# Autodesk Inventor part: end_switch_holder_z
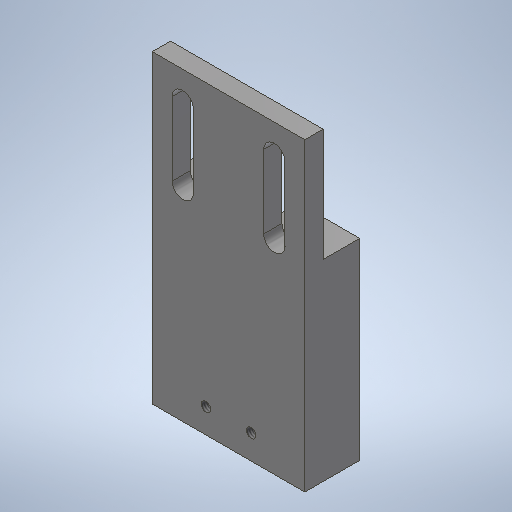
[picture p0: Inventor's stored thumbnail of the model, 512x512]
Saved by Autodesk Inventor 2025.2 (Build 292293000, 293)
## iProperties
Created: 2025-04
Part Number: end_switch_holder_z
Material: 1.0037 S235JR
Document SubType Name: Modeling
Designer: BennF
Density: 7.85 g/cm^3
Appearance: Stahl
Author: BennF
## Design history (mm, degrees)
sketch "Sketch2"
  geometry: L1 (7.5, 45.25)-(7.5, 33.25); L2 (5.75, 45.25)-(5.75, 33.25); L3 (9.25, 33.25)-(9.25, 45.25); L4 (-7.5, 45.25)-(-7.5, 33.25); L5 (-9.25, 45.25)-(-9.25, 33.25); L6 (-5.75, 33.25)-(-5.75, 45.25); L7 (12.5, 50)-(12.5, 0); L8 (12.5, 50)-(-12.5, 50); L9 (-12.5, 50)-(-12.5, 0); L10 (-12.5, 0)-(12.5, 0); L11 (7.5, 39.25)-(-7.5, 39.25); A1 r 1.75 centre (7.5, 45.25) between (9.25, 45.25) and (5.75, 45.25); A2 r 1.75 centre (7.5, 33.25) between (5.75, 33.25) and (9.25, 33.25); A3 r 1.75 centre (-7.5, 45.25) between (-5.75, 45.25) and (-9.25, 45.25); A4 r 1.75 centre (-7.5, 33.25) between (-9.25, 33.25) and (-5.75, 33.25); 4 further points
  constraints: 26 end point, 9 point on circle, 8 tangent, 4 centre point, 4 midpoint, 3 parallel, 3 perpendicular, 2 horizontal alignment, 2 vertical, 1 coincident, 1 equal radius, 1 horizontal, 1 vertical alignment
  dimensions: "d0" = 50 distance of L7.start L7.end; "d1" = 25 distance of L7.start L8.end; "d2" = 15 distance of L11.start L11.end; "d3" = 1.75 radius of A1; "d4" = 3 distance from line of L8 point (7.5, 47); "d5" = 12 distance of L1.start L1.end
extrude "Extrusion1" new body sketch "Sketch2" distance "d6" = 3; taper "d7" = 0 deg
sketch "Sketch3"
  geometry: L1 (12.5, 0)-(-12.5, 0) reference; L2 (7, 0)-(7, -15); L3 (7, -15)-(2.5, -15); L4 (2.5, -15)-(2.5, -31.5); L5 (-7, 0)-(-7, -15); L6 (-7, -15)-(-2.5, -15); L7 (-2.5, -15)-(-2.5, -31.5); L8 (12.5, -31.5)-(-12.5, -31.5); L9 (-12.5, 0)-(-12.5, -50) reference; L10 (12.5, -50)-(12.5, 0) reference; L11 (2.5, -15)-(-2.5, -15); A1 r 1.75 centre (7.5, -33.25) between (9.25, -33.25) and (5.75, -33.25) reference; 6 further points
  constraints: 16 end point, 7 point on line, 4 perpendicular, 3 midpoint, 2 horizontal, 2 point on circle, 2 vertical, 1 collinear, 1 horizontal alignment, 1 vertical alignment
  dimensions: "d8" = 14 distance between parallel lines of L5 L2; "d9" = 15 distance of L2.start L2.end; "d10" = 5 distance between parallel lines of L7 L4
extrude "Extrusion2" join sketch "Sketch3" distance "d11" = 6; taper "d12" = 0 deg
sketch "Sketch4"
  geometry: L1 (3.7, -4)-(-3.7, -4); L2 (7, 0)-(-7, 0) reference; 3 further points
  constraints: 2 end point, 2 midpoint, 1 horizontal, 1 horizontal alignment, 1 vertical alignment
  dimensions: "d20" = 7.4 distance of L1.start L1.end; "d21" = 4 distance between parallel lines of L2 L1
hole "Hole1" sketch "Sketch4" at (3.7, -4), (-3.7, -4) diameter "d13" = 1.567; stored, may be unused: countersink angle "d17" = 90 deg, drill point angle "d19" = 0 deg; dims "d14" = 4, "d15" = 4, "d16" = 6.7, "d18" = 6.3
body "Solid1"
